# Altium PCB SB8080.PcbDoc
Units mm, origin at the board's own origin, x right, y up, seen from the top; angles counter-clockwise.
Board outline 80 x 80 mm, 2 copper layers (Top Layer, Bottom Layer); 0 components, 0 nets, 4 pads, 0 vias.
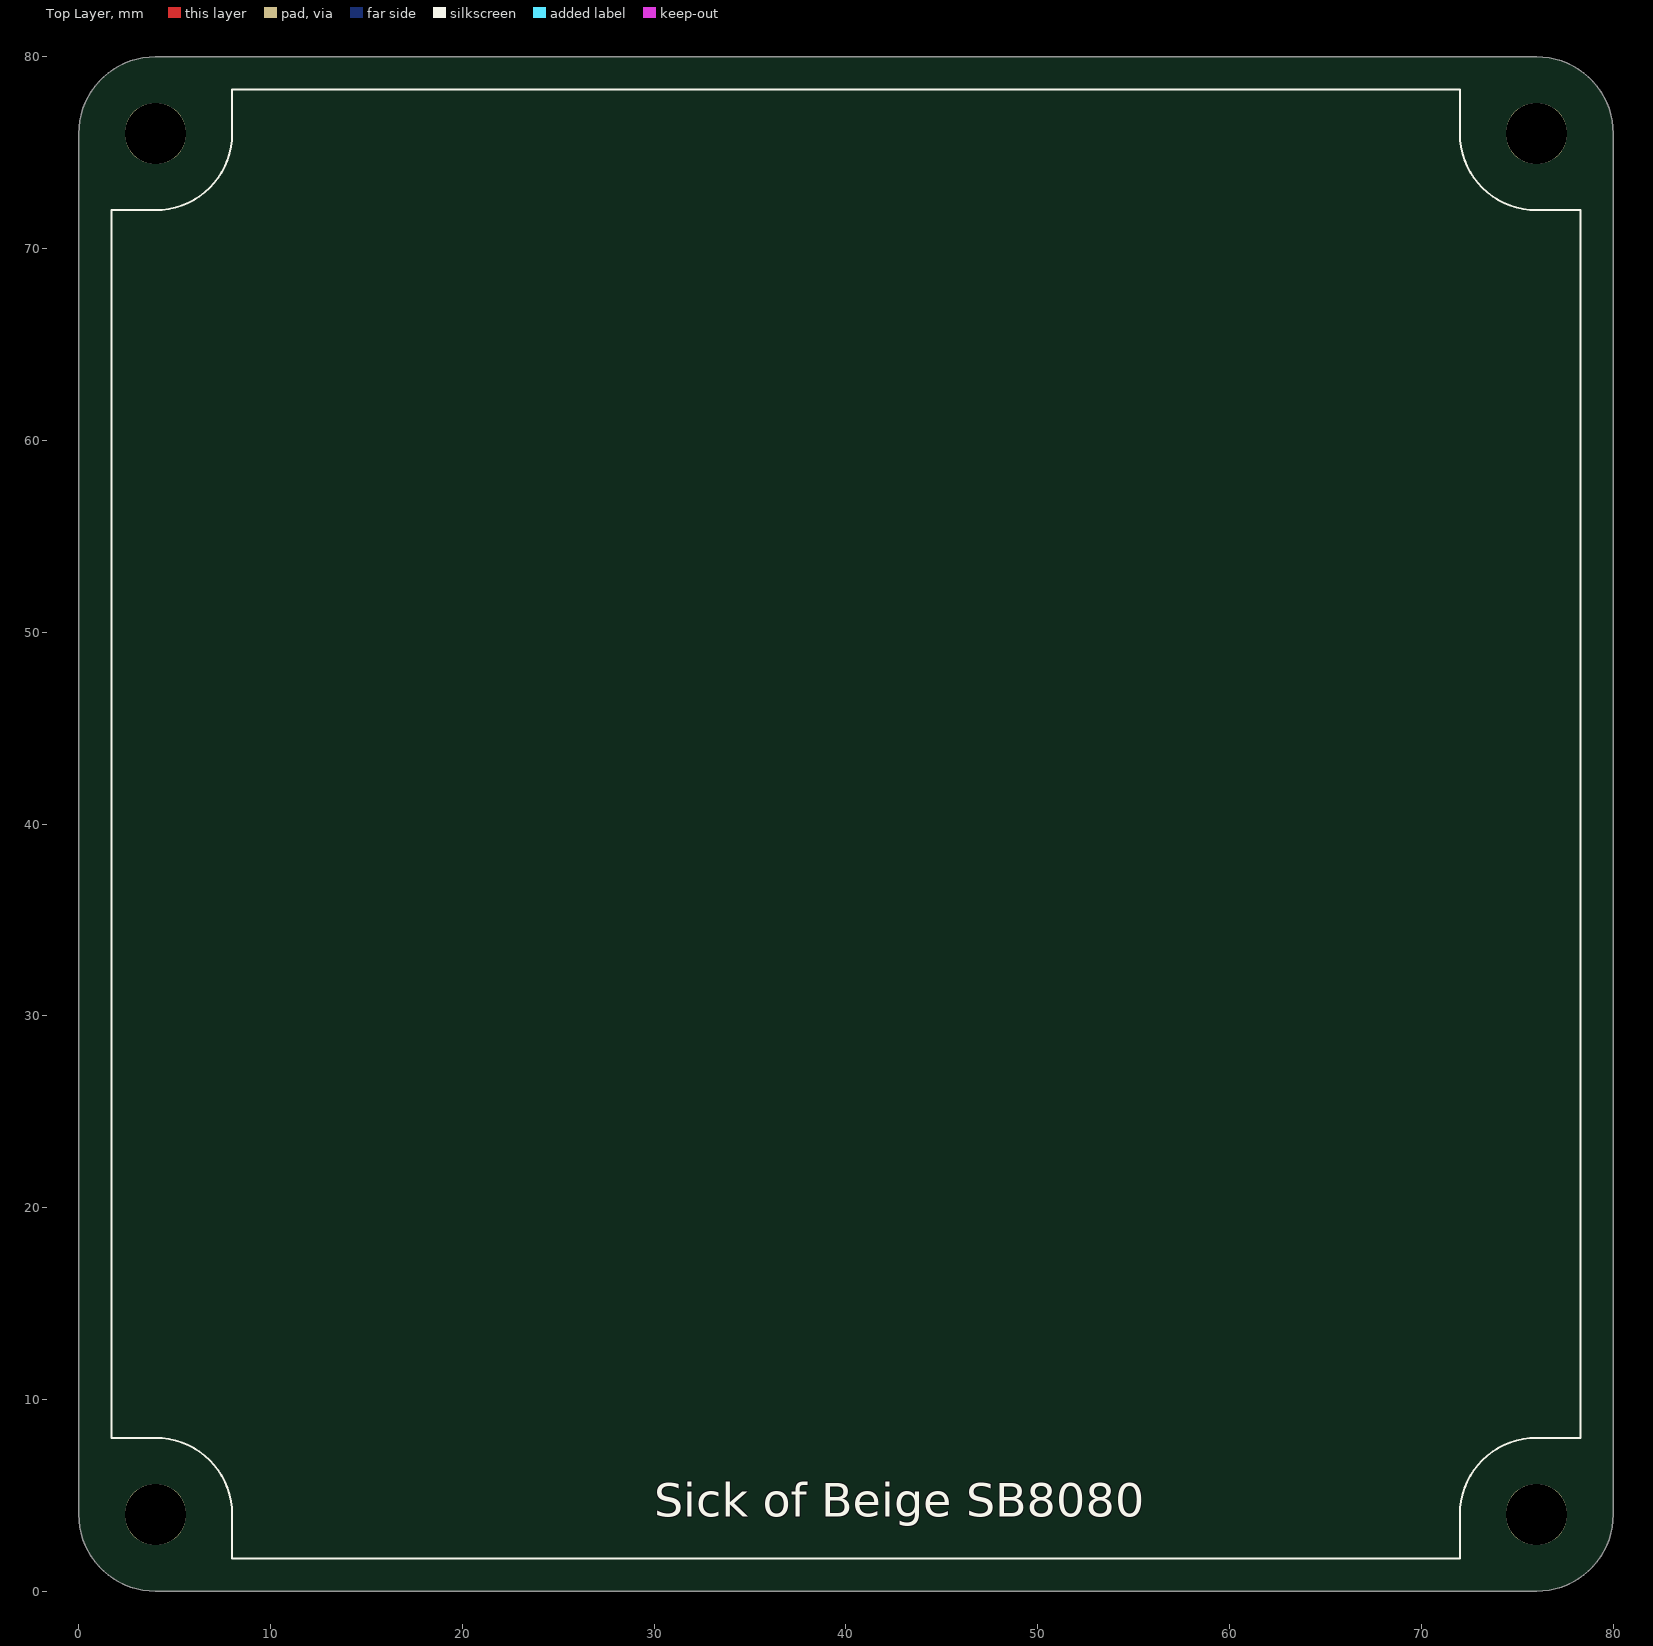
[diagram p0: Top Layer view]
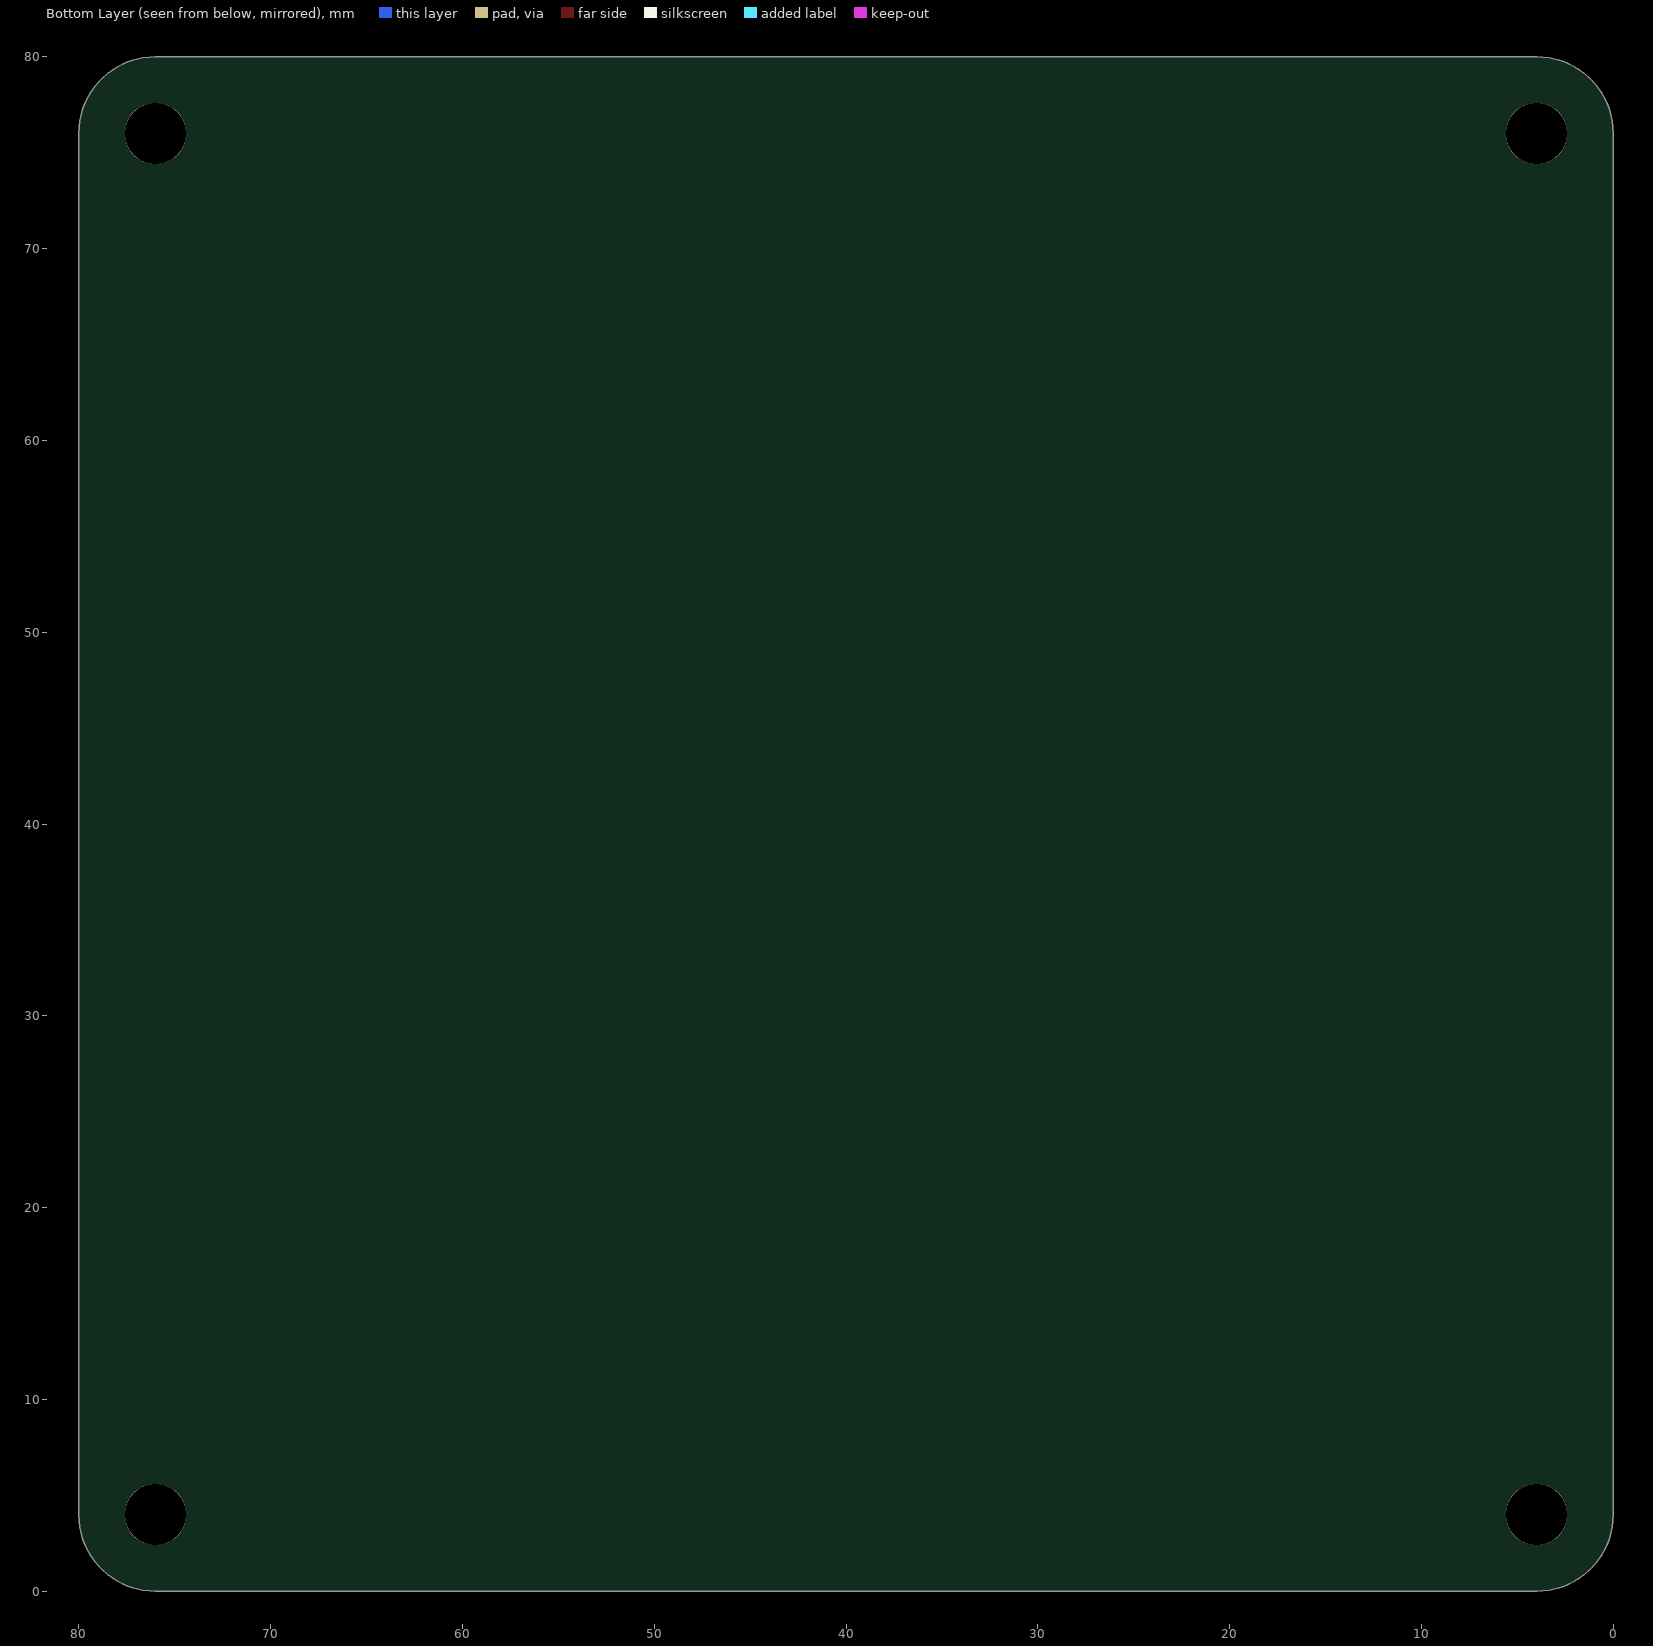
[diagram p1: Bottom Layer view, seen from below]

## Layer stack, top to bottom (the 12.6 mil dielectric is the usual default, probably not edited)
Top Layer: signal copper 0.0356
Dielectric: dielectric 0.32, FR-4, Dk 4.8
Bottom Layer: signal copper 0.0356

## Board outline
4,0 cw(c4,4) 0,4 0,76 cw(c4,76) 4,80 76,80 cw(c76,76) 80,76 80,4 cw(c76,4) 76,0

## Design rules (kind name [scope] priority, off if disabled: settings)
Clearance [All] p1: gap=0.254
PolygonConnect [All] p1: connectstyle=Relief reliefconductorwidth=0.254 reliefentries=4 polygonreliefangle="90 Angle" airgapwidth=0.254
RoutingVias [All] p1: holewidth=0.711 width=1.27 viastyle="Through Hole" minholewidth=0.711 minwidth=1.27 maxholewidth=0.711 maxwidth=1.27
SolderMaskExpansion [All] p1: expansion=0.102
Width [All] p1: maxlimit=0.254 minlimit=0.254 preferedwidth=0.254
28 further rules are at their usual default settings.

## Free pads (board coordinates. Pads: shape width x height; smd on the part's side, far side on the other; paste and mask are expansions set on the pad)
  round 3.2 hole 3.2 unplated: 0(4,4) 1(4,76) 2(76,76) 3(76,4)

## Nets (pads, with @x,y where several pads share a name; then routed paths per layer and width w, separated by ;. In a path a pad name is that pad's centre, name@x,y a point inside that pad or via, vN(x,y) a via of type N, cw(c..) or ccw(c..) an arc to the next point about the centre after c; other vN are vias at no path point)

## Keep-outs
Top Overlay:
  lines w0.102: 1.7,8 4,8 cw(c4,4) 8,4 8,1.7 72,1.7 72,4 cw(c76,4) 76,8 78.3,8 78.3,72 76,72 cw(c76,76) 72,76 72,78.3 8,78.3 8,76 cw(c4,76) 4,72 1.7,72 1.7,8

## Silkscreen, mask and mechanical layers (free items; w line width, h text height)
Top Overlay:
  text "Sick of Beige SB8080" at 30,3.3 h3
Mechanical 1:
  the board outline again, w0.102
Mechanical 4:
  circle w0.102: c76,76 r1.6
  circle w0.102: c4,76 r1.6
  circle w0.102: c4,4 r1.6
  circle w0.102: c76,4 r1.6
  lines w0.102: 0,40 80,40 ; 40,0 40,80

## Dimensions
76,80 to 76,0 on Mechanical 3
0,4 to 80,4 on Mechanical 3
